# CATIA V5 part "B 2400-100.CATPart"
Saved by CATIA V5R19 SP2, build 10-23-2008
Part number: B 2400-100
Bounding box of the stored display mesh (mm): x -37.351 to 37.351, y -37.351 to 37.351, z 0 to 310
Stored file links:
  C:\Users\Bora\Desktop\3D Katı model\B serisi\B 2400\B 2400-100.CATPart
  C:\Program Files\Dassault Systemes\B19\intel_a\reffiles\standard\MetricThickPitch.txt
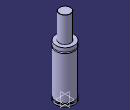
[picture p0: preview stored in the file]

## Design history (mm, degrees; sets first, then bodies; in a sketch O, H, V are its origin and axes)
Body1 (main body)
  Sketch1 on yz-plane, origin (0, 0, 0), H (0, 1, 0), V (0, 0, 1)
    point P3 (22.5, 309)
    point P5 (22.5, 309)
    point P10 (37.5, 186.5)
    point P11 (37.5, 191.5)
    point P13 (37.5, 191.5)
    point P14 (37.5, 186.5)
    line L1 (37.5, 0) -> (37.5, 8)
    line L2 (22.5, 309) -> (22.5, 207)
    arc A1 centre (21.5, 309) radius 1 from (22.5, 309) to (21.5, 310) ccw
    line L3 (33.5, 13) -> (33.5, 8)
    line L4 (37.5, 13) -> (37.5, 186.5)
    line L5 (37.5, 191.5) -> (37.5, 207)
    arc A2 centre (37.5, 189) radius 2.5 from (37.5, 191.5) to (37.5, 186.5) ccw
    line L6 (21.5, 310) -> (0, 310)
    point P15 (0, 310)
    line L7 (22.5, 207) -> (37.5, 207)
    line L8 (0, 0) -> (37.5, 0)
    line L9 (33.5, 13) -> (37.5, 13)
    line L10 (33.5, 8) -> (37.5, 8)
    coincidence: P15 V, P3 P5, P10 P14, P11 P13
    tangency: L6 A1
    horizontal: L7 H, L8 H, L9 H, L10 H
  Shaft1: profile Sketch1, axis Sketch1.V, angle 360
  Sketch2 on face of Shaft1 from Sketch1.L8, origin (0, 0, 0), H (1, 0, 0), V (0, -1, 0)
    point P1 (20, 0)
    distance P1 V = 20
  Hole1: placed by Sketch2, at (20, 0, 0) direction (0, 0, 1), diameter 6.647, depth 13, threaded "M8", thread diameter 8, thread depth 13, pitch 1.25
  CircPattern1: of Hole1, instances 4, angular step 90, axis from xy-plane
